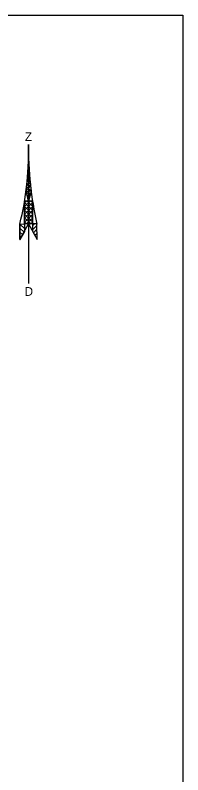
# Model space of a CAD drawing. Extents: x 503353 to 504004, y 304662 to 305049.
# Drawn here: x 503823.5 to 503840.3, y 304813.5 to 304889.8 of the extents above; entities that cross this region are included whole.
import ezdxf

# ---------------------------------------------------------------- set-up
doc = ezdxf.new("R2010")
doc.units = 0
doc.layers.add('RAMI_PLAN_####_TKST_#', color=7, linetype='Continuous')

msp = doc.modelspace()

# ---------------------------------------------------------------- linework, layer by layer
at = {"layer": 'RAMI_PLAN_####_TKST_#'}
for p, q in [((503824.818, 304876.817), (503824.818, 304862.847)), ((503824.821, 304875.116), (503824.843, 304875.094)), ((503824.775, 304874.315), (503824.877, 304874.415)), ((503824.778, 304874.379), (503824.885, 304874.276)), ((503824.795, 304874.725), (503824.858, 304874.783)), ((503824.798, 304874.747), (503824.862, 304874.686)), ((503824.682, 304873.062), (503824.956, 304873.324)), ((503824.717, 304873.487), (503824.925, 304873.683)), ((503824.73, 304873.648), (503824.947, 304873.442)), ((503824.75, 304873.907), (503824.896, 304874.04)), ((503824.758, 304874.006), (503824.911, 304873.865)), ((503824.584, 304872.191), (503825.019, 304872.606)), ((503824.626, 304872.582), (503825.069, 304872.158)), ((503824.632, 304872.629), (503824.987, 304872.965)), ((503824.665, 304872.932), (503825.02, 304872.596)), ((503824.702, 304873.288), (503824.981, 304873.02)), ((503824.587, 304872.233), (503825.001, 304871.836)), ((503824.644, 304871.86), (503825.06, 304872.26)), ((503824.717, 304871.543), (503824.993, 304871.806)), ((503824.43, 304870.586), (503825.03, 304871.156)), ((503824.435, 304870.977), (503824.621, 304871.156)), ((503824.642, 304871.156), (503825.218, 304870.608)), ((503824.664, 304871.771), (503824.92, 304871.524)), ((503824.779, 304871.269), (503824.839, 304871.213)), ((503824.789, 304871.225), (503824.861, 304871.295)), ((503825.05, 304871.156), (503825.215, 304870.998)), ((503824.424, 304869.803), (503825.218, 304870.558)), ((503824.428, 304870.196), (503825.215, 304870.944)), ((503824.43, 304870.577), (503825.219, 304869.831)), ((503824.435, 304870.964), (503825.218, 304870.22)), ((503824.416, 304869.018), (503825.219, 304869.781)), ((503824.42, 304869.409), (503825.218, 304870.171)), ((503824.424, 304869.809), (503825.221, 304869.052)), ((503824.428, 304870.196), (503825.219, 304869.442)), ((503823.947, 304868.797), (503823.969, 304867.249)), ((503823.951, 304868.797), (503824.414, 304868.361)), ((503823.969, 304867.249), (503824.83, 304868.822)), ((503824.329, 304868.827), (503824.415, 304868.745)), ((503824.416, 304869.038), (503824.636, 304868.831)), ((503824.42, 304869.426), (503825.046, 304868.831)), ((503824.627, 304868.831), (503825.219, 304869.393)), ((503824.83, 304868.822), (503825.688, 304867.249)), ((503825.033, 304868.831), (503825.221, 304869.008)), ((503825.221, 304868.637), (503825.418, 304868.827)), ((503825.688, 304867.249), (503825.666, 304868.822)), ((503823.953, 304868.407), (503824.381, 304868.006)), ((503823.958, 304868.014), (503824.242, 304867.748)), ((503825.219, 304868.25), (503825.669, 304868.676)), ((503825.308, 304867.942), (503825.673, 304868.294)), ((503823.965, 304867.618), (503824.102, 304867.49)), ((503823.969, 304867.256), (503823.979, 304867.264)), ((503825.447, 304867.69), (503825.677, 304867.908)), ((503825.586, 304867.435), (503825.684, 304867.525)), ((503825.688, 304867.251), (503825.688, 304867.251))]:
    msp.add_line(p, q, dxfattribs=at)
for points in [[(503840.281, 304747.19), (503643.096, 304747.19), (503643.096, 304889.794), (503840.281, 304889.794)], [(503824.816, 304871.116), (503824.577, 304872.148), (503824.687, 304873.103), (503824.757, 304873.977), (503824.819, 304875.116), (503824.84, 304875.116), (503824.896, 304874.04), (503825.012, 304872.672), (503825.074, 304872.123)], [(503824.436, 304871.156), (503825.215, 304871.156), (503825.221, 304868.829), (503824.415, 304868.834)], [(503824.415, 304868.834), (503824.413, 304868.059), (503823.969, 304867.249), (503823.947, 304868.797)], [(503825.221, 304868.829), (503825.219, 304868.099), (503825.688, 304867.249), (503825.666, 304868.822)]]:
    msp.add_lwpolyline(points, close=True, dxfattribs=at)
for centre, major_axis, start_param, end_param in [((503792.485, 304875.933), (32.345, 0), 6.048896, 6.311872), ((503863.155, 304876.45), (-38.341, 0), 6.273156, 6.494161)]:
    msp.add_ellipse(centre, major_axis=major_axis, ratio=0.950423, start_param=start_param, end_param=end_param, dxfattribs=at)

# ---------------------------------------------------------------- texts
for s, p in [('Z', (503824.463, 304877.158)), ('D', (503824.429, 304861.604))]:
    msp.add_text(s, height=0.878, rotation=360, dxfattribs=at).set_placement(p)

doc.saveas('drawing.dxf')
